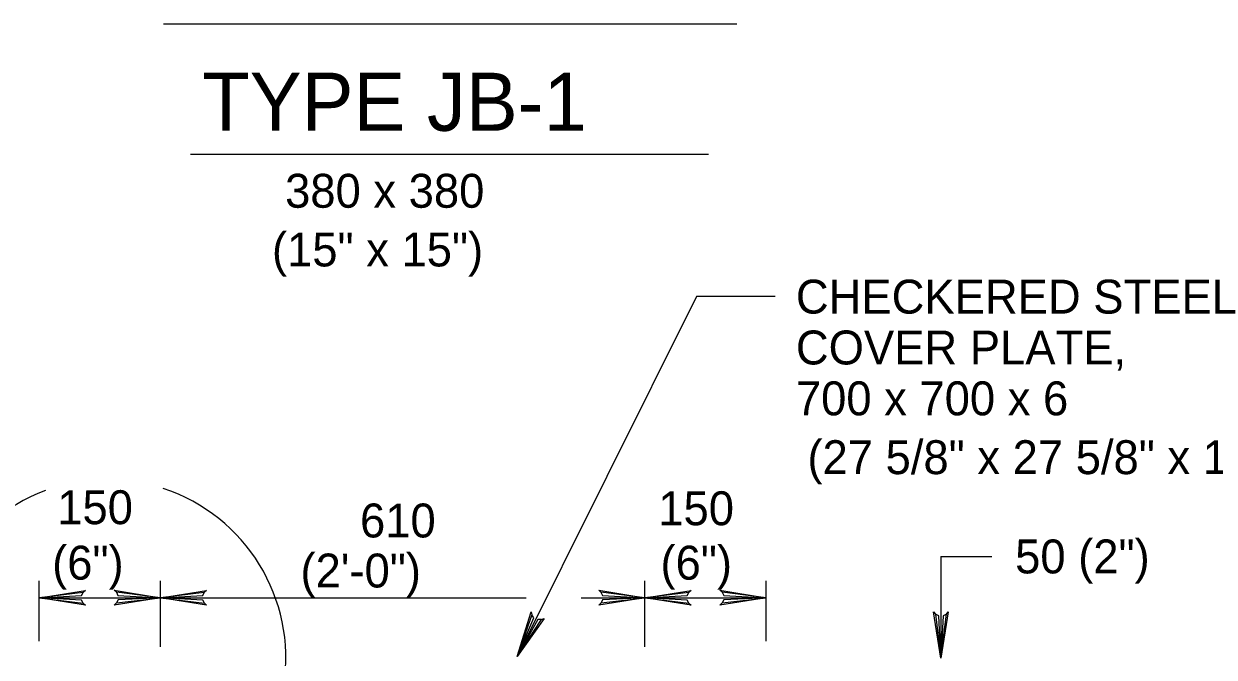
# Model space of a CAD drawing. Extents: x 638447 to 639352, y 298406 to 299000.
# Drawn here: x 638720.2 to 638838.1, y 298774.1 to 298836.9 of the extents above; entities that cross this region are included whole.
import ezdxf

# ---------------------------------------------------------------- set-up
doc = ezdxf.new("R2010")
doc.units = 0
for name, color, linetype in [('1', 7, 'Continuous'), ('2', 7, 'Continuous'), ('3', 7, 'Continuous')]:
    doc.layers.add(name, color=color, linetype=linetype)

msp = doc.modelspace()

# ---------------------------------------------------------------- linework, layer by layer
at = {"layer": '2'}
for p, q in [((638786.846125, 298809.85975), (638769.082375, 298774.168)), ((638794.643375, 298809.85975), (638786.846125, 298809.85975)), ((638811.068375, 298784.084), (638811.068375, 298774.004)), ((638721.754375, 298775.684), (638721.754375, 298781.67)), ((638733.754375, 298775.128), (638733.754375, 298781.67)), ((638781.754375, 298775.128), (638781.754375, 298781.67)), ((638793.754375, 298775.684), (638793.754375, 298781.67)), ((638721.754375, 298779.99), (638733.754375, 298779.99)), ((638733.754375, 298779.99), (638769.988625, 298779.99)), ((638775.443375, 298779.99), (638781.754375, 298779.99)), ((638781.754375, 298779.99), (638793.754375, 298779.99))]:
    msp.add_line(p, q, dxfattribs=at)
for points in [[(638811.068375, 298784.084), (638816.108375, 298784.084)], [(638726.112375, 298779.444), (638725.950375, 298779.76), (638721.754375, 298779.99), (638726.112375, 298779.444), (638726.336375, 298779.252), (638721.754375, 298779.99), (638725.946375, 298780.198), (638726.100375, 298780.51), (638721.754375, 298779.99), (638726.336375, 298780.718), (638726.100375, 298780.51)], [(638729.394375, 298780.538), (638729.556375, 298780.222), (638733.754375, 298779.99), (638729.394375, 298780.538), (638729.170375, 298780.73), (638733.754375, 298779.99), (638729.560375, 298779.784), (638729.406375, 298779.472), (638733.754375, 298779.99), (638729.170375, 298779.262), (638729.406375, 298779.472)], [(638738.112375, 298779.444), (638737.950375, 298779.76), (638733.754375, 298779.99), (638738.112375, 298779.444), (638738.336375, 298779.252), (638733.754375, 298779.99), (638737.946375, 298780.198), (638738.100375, 298780.51), (638733.754375, 298779.99), (638738.336375, 298780.718), (638738.100375, 298780.51)], [(638777.394375, 298780.538), (638777.556375, 298780.222), (638781.754375, 298779.99), (638777.394375, 298780.538), (638777.170375, 298780.73), (638781.754375, 298779.99), (638777.560375, 298779.784), (638777.406375, 298779.472), (638781.754375, 298779.99), (638777.170375, 298779.262), (638777.406375, 298779.472)], [(638786.112375, 298779.444), (638785.950375, 298779.76), (638781.754375, 298779.99), (638786.112375, 298779.444), (638786.336375, 298779.252), (638781.754375, 298779.99), (638785.946375, 298780.198), (638786.100375, 298780.51), (638781.754375, 298779.99), (638786.336375, 298780.718), (638786.100375, 298780.51)], [(638789.394375, 298780.538), (638789.556375, 298780.222), (638793.754375, 298779.99), (638789.394375, 298780.538), (638789.170375, 298780.73), (638793.754375, 298779.99), (638789.560375, 298779.784), (638789.406375, 298779.472), (638793.754375, 298779.99), (638789.170375, 298779.262), (638789.406375, 298779.472)], [(638771.514375, 298777.826), (638771.158375, 298777.822), (638769.082375, 298774.168), (638771.514375, 298777.826), (638771.784375, 298777.94), (638769.082375, 298774.168), (638770.764375, 298778.014), (638770.554375, 298778.29), (638769.082375, 298774.168), (638770.472375, 298778.594), (638770.554375, 298778.29)], [(638811.614375, 298778.362), (638811.300375, 298778.2), (638811.068375, 298774.004), (638811.614375, 298778.362), (638811.806375, 298778.586), (638811.068375, 298774.004), (638810.860375, 298778.198), (638810.548375, 298778.35), (638811.068375, 298774.004), (638810.340375, 298778.586), (638810.548375, 298778.35)]]:
    msp.add_lwpolyline(points, dxfattribs=at)
msp.add_arc((638728.491221, 298774.003748), 17.699271, 110.26046667, 71.742925, dxfattribs=at)
at = {"layer": '3'}
for p, q in [((638734.062125, 298836.8725), (638790.871125, 298836.8725)), ((638736.731375, 298823.96575), (638788.043375, 298823.96575))]:
    msp.add_line(p, q, dxfattribs=at)

# ---------------------------------------------------------------- texts
at = {"layer": '1'}
for s, p in [('(15" x 15")', (638744.807625, 298812.8265)), ('(27 5/8" x 27 5/8" x 1/4")', (638797.850885, 298792.2405)), ('(6")', (638723.032625, 298781.7865)), ('(6")', (638783.294375, 298781.7865)), ('(2\'-0")', (638747.631125, 298781.0065))]:
    msp.add_text(s, height=3.36, dxfattribs=at).set_placement(p)
at = {"layer": '3'}
for s, height, p in [('TYPE JB-1', 5.76, (638737.903375, 298826.26575)), ('380 x 380', 3.36, (638746.110375, 298818.64275)), ('CHECKERED STEEL', 3.359988, (638796.707125, 298808.15175)), ('COVER PLATE,', 3.359988, (638796.707125, 298803.11175)), ('700 x 700 x 6', 3.359988, (638796.707125, 298798.07175)), ('150', 3.36, (638723.537875, 298787.28125)), ('150', 3.36, (638783.078125, 298787.1775)), ('610', 3.36, (638753.532625, 298785.9665)), ('50 (2")', 3.36, (638818.424375, 298782.404))]:
    msp.add_text(s, height=height, dxfattribs=at).set_placement(p)

doc.saveas('drawing.dxf')
